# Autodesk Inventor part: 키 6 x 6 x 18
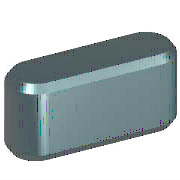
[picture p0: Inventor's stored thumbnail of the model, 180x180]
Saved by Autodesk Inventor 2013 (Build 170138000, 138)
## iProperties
Created: 2012-02
Part Number: 키 6 x 6 x 18
Material: 강철, 연강
Description: 키 및 해당 키홈
Document SubType Name: Modeling
Standard: KS B 1311
Designer: mduedu
Standards Organization: KS
Language: ko-KR
Size Designation: 6 x 6 x 18
Categories: <MemberInstance><Categories><Category DisplayName="샤프트 부품" InternalName="7f7aeb1f-a693-4053-b835-cee3144e0d98" Mnemonic="SHFT"><Category DisplayName="키" Interna
Density: 1 g/cm^3
IsCustomPart: 1
Author: mduedu
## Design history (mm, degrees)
workplane "Work Plane1"
workplane "Work Plane2"
sketch "스케치1"
  geometry: L1 (3, 3)-(15, 3); L2 (15, -3)-(3, -3); L3 (0, 9.4)-(0, -7.4) reference; L4 (-5, 0)-(30, 0) reference; L5 (18, 0)-(18, 7); A1 r 3 centre (3, 0) between (3, 3) and (3, -3); A2 r 3 centre (15, 0) between (15, -3) and (15, 3)
  constraints: 6 end point, 5 point on circle, 4 tangent, 3 point on line, 2 centre point, 1 horizontal, 1 parallel, 1 perpendicular
  dimensions: "d0" = 3 radius of A1 (= 0.5 x PB); "d13" = 3 radius of A2 (= 0.5 x PB); "d14" = 18 distance between parallel lines of L5 L3 (= NLG)
extrude "본체1" new body sketch "스케치1" taper "d3" = 0 deg; stored distance "d4" = 10
workplane "Work Plane3"
body "Solid1"
chamfer "모따기1" distance "d8" = 0.4 (= PHH); stored, may be unused: second distance "d9" = 0.4 (= PHH), angle "d15" = 45 deg
other parameters: "d1" = -3.5 (= -PNT), "d2" = 2.5 (= PH - PNT), "NLG" = 18 [user parameter; used in 3 equation terms], "PB" = 6 [user parameter; used in 2 equation terms], "PNT" = 3.5 [user parameter; used in 2 equation terms], "PH" = 6 [user parameter; used in 1 equation term], "PHH" = 0.4 [user parameter; used in 2 equation terms], "d10" = 0, "d16" = 0, "d17" = 0, "d18" = 0, "WDMIN" = 17 [user parameter], "PLB2" = 18 (= NLG) [user parameter], "WDMAX" = 22 [user parameter], "PLB1" = 18 (= NLG) [user parameter], "RR" = 0.16 [user parameter], "PUEB" = 2.8 [user parameter]
